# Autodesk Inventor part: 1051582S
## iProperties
Shininess: 64.0
Length Units: 11269
Angle Units: 11279
Time Units: 11290
Mass Units: 11283
Length Display Precision: 3
Angle Display Precision: 2
Compacted: True
Part Number: 1051582S
Document SubType Name: Modeling
Created: 2003-02
Material: Standard
Designer: W. Holzwarth
Density: 0.0
Volumn: 0.0
Area: 0.0
PropertySet Name: Model Information
Control State: 0
Master: False
Checked Out: False
Author: W. Holzwarth
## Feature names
1. Drehung1 [Revolution]
2. Extrusion1
3. Drehung2 [Revolution]
4. Spiegeln1 [Mirror]
5. Extrusion3
6. Rundung1 [Fillet]
7. Rundung2 [Fillet]
8. Rundung3 [Fillet]
9. Bohrung1 [Hole]
10. Rundung4 [Fillet]
